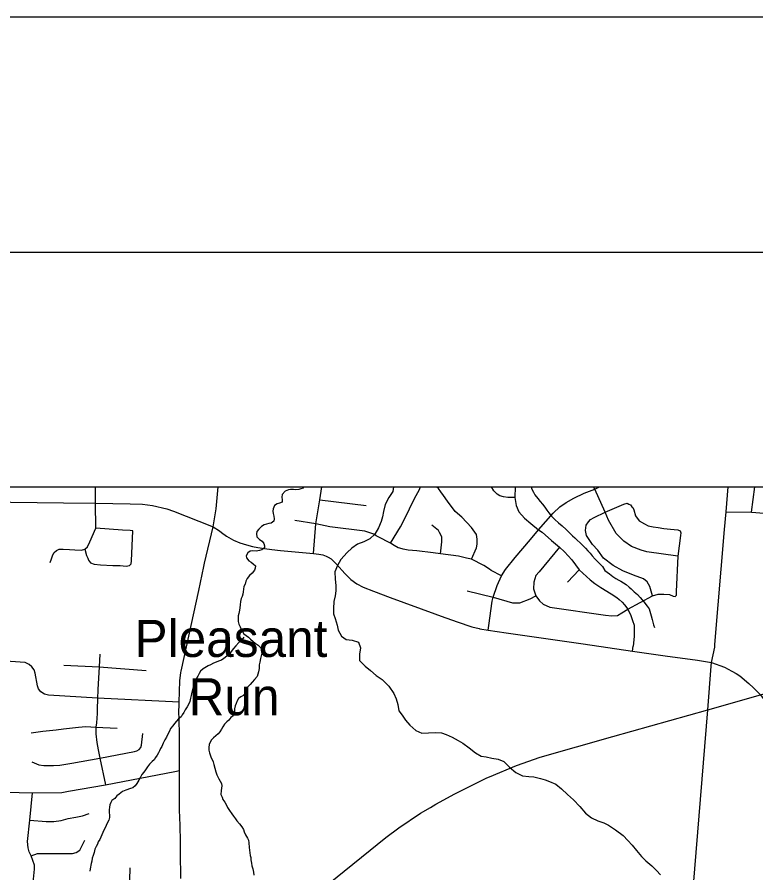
# Model space of a CAD drawing. Extents: x 0 to 34, y 0 to 22.
# Drawn here: x 5.399 to 6.973, y 20.179 to 22 of the extents above; entities that cross this region are included whole.
import ezdxf

# ---------------------------------------------------------------- set-up
doc = ezdxf.new("R2010")
doc.units = 0
for name, color, linetype in [('GM_X_City_Street', 7, 'Continuous'), ('GM_X_County_Road', 7, 'Continuous'), ('GM_X_Interstate_Route', 7, 'Continuous'), ('GM_X_Minor_River', 7, 'Continuous'), ('GM_X_Township_Subdivision', 7, 'Continuous'), ('GM_X_Unincorporated_Text', 7, 'Continuous'), ('GM_X_US_Route', 7, 'Continuous'), ('SH_Border', 7, 'Continuous'), ('SH_Cut_Line', 7, 'Continuous'), ('SH_Data', 7, 'Continuous')]:
    doc.layers.add(name, color=color, linetype=linetype)

msp = doc.modelspace()

# ---------------------------------------------------------------- linework, layer by layer
at = {"layer": 'GM_X_City_Street'}
for points in [[(6.3832, 20.6986), (6.3849, 20.6981), (6.4022, 20.695), (6.4405, 20.6893), (6.605, 20.6658), (6.7096, 20.6506), (6.7795, 20.6409), (6.8483, 20.6312), (6.8782, 20.6263), (6.9055, 20.6167), (6.9213, 20.6082), (6.9304, 20.6028)], [(6.4022, 20.695), (6.4035, 20.7049)], [(6.7096, 20.6506), (6.7109, 20.6612)], [(6.8782, 20.6263), (6.8849, 20.6592), (6.8854, 20.665)], [(6.7405, 19.0079), (6.7405, 19.0079), (6.7657, 19.288), (6.7742, 19.3827), (6.7997, 19.6706), (6.8028, 19.7088), (6.8332, 20.0742), (6.8703, 20.5257), (6.8776, 20.6185)], [(6.8776, 20.6185), (6.8782, 20.6263)], [(6.9304, 20.6028), (6.9384, 20.598), (6.9578, 20.5819), (6.9677, 20.5727), (6.9821, 20.5579), (6.9976, 20.5368), (7.0156, 20.5042), (7.0369, 20.4622), (7.0524, 20.431), (7.0619, 20.4131), (7.0736, 20.3904)], [(5.7352, 20.3947), (5.7449, 20.3966)]]:
    msp.add_lwpolyline(points, dxfattribs=at)
at = {"layer": 'GM_X_County_Road'}
for points in [[(6.8854, 20.665), (6.9059, 20.9098), (6.9091, 20.9473), (6.9137, 21)], [(5.3429, 20.9683), (5.3857, 20.9676), (5.4981, 20.9661), (5.5663, 20.9653), (5.6398, 20.9643), (5.6661, 20.9637), (5.6877, 20.9605), (5.7182, 20.9531), (5.7325, 20.9484), (5.786, 20.9271), (5.8166, 20.9148)], [(5.8166, 20.9148), (5.8302, 20.9069), (5.8343, 20.9031), (5.8448, 20.8953), (5.8598, 20.8869), (5.8736, 20.881), (5.8879, 20.8765), (5.9007, 20.8732), (5.9118, 20.8713), (5.926, 20.8693), (5.942, 20.8668), (5.9602, 20.8648), (6.0301, 20.8581), (6.0417, 20.8568), (6.0502, 20.8553), (6.0573, 20.8526), (6.0618, 20.8504), (6.0678, 20.8469), (6.0791, 20.8358), (6.0974, 20.8159), (6.1102, 20.8027), (6.1228, 20.7937), (6.1362, 20.7869), (6.1585, 20.7779), (6.194, 20.7649), (6.2889, 20.7299), (6.3022, 20.7249), (6.3362, 20.7129), (6.3678, 20.7026), (6.3832, 20.6986)], [(5.375, 20.3502), (5.4319, 20.3493), (5.4945, 20.35), (5.5087, 20.3522), (5.5871, 20.3662), (5.7352, 20.3947)]]:
    msp.add_lwpolyline(points, dxfattribs=at)
at = {"layer": 'GM_X_Interstate_Route'}
for points in [[(6.4056, 20.3832), (6.4626, 20.4073), (6.5132, 20.4247), (6.6681, 20.4691), (6.8703, 20.5257), (6.9821, 20.5579), (7.3247, 20.6555), (7.624, 20.7407), (7.6888, 20.7597), (7.7242, 20.769), (7.855, 20.8068), (7.91, 20.8216)], [(6.2913, 20.3246), (6.3311, 20.3471), (6.3995, 20.3807), (6.4056, 20.3832)], [(5.8297, 19.9667), (5.8374, 19.973), (5.8497, 19.9841), (5.9922, 20.0984), (6.1844, 20.2537), (6.2121, 20.2744), (6.2584, 20.306), (6.2797, 20.318), (6.2913, 20.3246)]]:
    msp.add_lwpolyline(points, dxfattribs=at)
at = {"layer": 'GM_X_Minor_River'}
for points in [[(5.9698, 20.9909), (5.9636, 20.9842), (5.9627, 20.9781), (5.9637, 20.9728), (5.964, 20.9674), (5.9579, 20.9653), (5.9533, 20.9638), (5.9475, 20.9605), (5.9444, 20.9534), (5.9439, 20.9488), (5.9445, 20.9435), (5.9459, 20.9377), (5.9466, 20.9324), (5.9461, 20.9275), (5.9403, 20.923), (5.9354, 20.922), (5.9254, 20.9191), (5.9197, 20.9158), (5.9142, 20.9099), (5.91, 20.9054), (5.9087, 20.9005), (5.9101, 20.894), (5.9153, 20.8885), (5.921, 20.8846), (5.9246, 20.8796), (5.9261, 20.875), (5.9264, 20.8704), (5.9202, 20.866), (5.9152, 20.8649), (5.9084, 20.8632), (5.9008, 20.8641), (5.8958, 20.8631), (5.8905, 20.8601), (5.8869, 20.8537), (5.8876, 20.8488), (5.8928, 20.8426), (5.8977, 20.8398), (5.9021, 20.8367), (5.9066, 20.8324), (5.9061, 20.8275), (5.9045, 20.8229), (5.8998, 20.8166), (5.894, 20.8114), (5.8894, 20.805), (5.8866, 20.7997), (5.8846, 20.7929), (5.8822, 20.788), (5.8813, 20.7827), (5.8808, 20.7766), (5.88, 20.7717), (5.8783, 20.7668), (5.8767, 20.7623), (5.8751, 20.7562), (5.8746, 20.7494), (5.8737, 20.7429), (5.8728, 20.738), (5.8712, 20.7308), (5.8703, 20.7255), (5.8698, 20.7187), (5.8701, 20.7133), (5.8715, 20.708), (5.874, 20.7022), (5.8762, 20.6976), (5.8795, 20.6922), (5.8821, 20.6876), (5.8869, 20.6837), (5.8918, 20.6806), (5.8963, 20.6763), (5.9018, 20.6712), (5.9063, 20.6677), (5.9123, 20.6634), (5.9175, 20.6584), (5.9208, 20.653), (5.9203, 20.6465), (5.9178, 20.6348), (5.9158, 20.6268), (5.9149, 20.6211), (5.9144, 20.6136), (5.9131, 20.6064), (5.9118, 20.6014), (5.9106, 20.5965), (5.9048, 20.5902), (5.9001, 20.5846), (5.8958, 20.5797), (5.89, 20.5737), (5.888, 20.5688), (5.8875, 20.5639), (5.8859, 20.5594), (5.8813, 20.5564), (5.8759, 20.5531), (5.8709, 20.5501), (5.8678, 20.5449), (5.8658, 20.5388), (5.8634, 20.5339), (5.8621, 20.5275), (5.862, 20.5222), (5.8615, 20.5176), (5.8596, 20.5131), (5.8545, 20.509), (5.8503, 20.5038), (5.8456, 20.5004)], [(6.0085, 21), (6.0083, 20.9977), (6.0037, 20.9959), (5.9991, 20.9945), (5.993, 20.9942), (5.9877, 20.9947), (5.9816, 20.9948), (5.9771, 20.9938), (5.9698, 20.9909)], [(6.201, 21), (6.1994, 20.9904), (6.1911, 20.9777), (6.1832, 20.9626), (6.1794, 20.9479), (6.1772, 20.9365), (6.1743, 20.9263), (6.1687, 20.9128), (6.1612, 20.8993), (6.1503, 20.8893), (6.1376, 20.8831), (6.1242, 20.8781), (6.1123, 20.8696), (6.1022, 20.8604), (6.0885, 20.8455), (6.0814, 20.8331), (6.0761, 20.8191), (6.0765, 20.8039), (6.0781, 20.7906), (6.0778, 20.7792), (6.0764, 20.7686), (6.0739, 20.7564), (6.0727, 20.7413), (6.0732, 20.7298), (6.0764, 20.7199), (6.0806, 20.7057), (6.083, 20.6954), (6.0899, 20.6827), (6.1, 20.6756), (6.1129, 20.6737), (6.1261, 20.67), (6.1303, 20.6577), (6.1281, 20.6441), (6.1282, 20.6304), (6.1408, 20.6183), (6.1519, 20.6093), (6.1642, 20.5987), (6.1769, 20.5904), (6.1906, 20.5757), (6.2016, 20.5602), (6.2063, 20.5487), (6.2102, 20.5372), (6.2121, 20.5238), (6.2191, 20.5141), (6.2265, 20.5037), (6.2357, 20.4928), (6.2487, 20.4815), (6.2611, 20.4762), (6.2755, 20.4767), (6.2904, 20.4774), (6.3033, 20.4768), (6.313, 20.4731), (6.3258, 20.4678), (6.3382, 20.4607), (6.3483, 20.4548), (6.3617, 20.4449), (6.3751, 20.4343), (6.3875, 20.4272), (6.3981, 20.4254), (6.4105, 20.4228), (6.4234, 20.4206), (6.4358, 20.4154), (6.448, 20.4033), (6.4614, 20.3923), (6.4753, 20.3852), (6.4893, 20.3837), (6.4999, 20.3827), (6.5139, 20.3793), (6.5237, 20.3768), (6.5334, 20.3731), (6.5462, 20.3675), (6.5589, 20.3573), (6.5715, 20.3456)], [(6.4943, 21), (6.4956, 20.9956), (6.4993, 20.9887), (6.5018, 20.9833), (6.5085, 20.9756), (6.5133, 20.969), (6.5181, 20.9632), (6.5229, 20.957), (6.5274, 20.9508), (6.5318, 20.945), (6.5374, 20.9381), (6.5444, 20.9307), (6.5519, 20.9237), (6.5601, 20.9171), (6.5683, 20.9093), (6.5757, 20.9023), (6.5821, 20.8961), (6.5869, 20.8915), (6.5921, 20.8868), (6.5981, 20.8813), (6.61, 20.8697), (6.6144, 20.8643), (6.6193, 20.8589), (6.6241, 20.8531), (6.63, 20.8465), (6.636, 20.8403), (6.646, 20.8309), (6.6508, 20.8225), (6.6609, 20.8154), (6.6676, 20.8096), (6.674, 20.8049), (6.6804, 20.8017), (6.6853, 20.7993), (6.6905, 20.7962), (6.6965, 20.7923), (6.7029, 20.7868), (6.7073, 20.7829), (6.7137, 20.7771), (6.7204, 20.7709), (6.7259, 20.7647)], [(6.7259, 20.7647), (6.7341, 20.7554), (6.7411, 20.7465), (6.7452, 20.7407), (6.7484, 20.7308), (6.7498, 20.7254), (6.7516, 20.7178), (6.753, 20.712), (6.7548, 20.7063), (6.7565, 20.7009)], [(5.8823, 20.6804), (5.8784, 20.6755), (5.8711, 20.6688), (5.8652, 20.6617), (5.8598, 20.6561), (5.8551, 20.6497), (5.8512, 20.6449), (5.8462, 20.64), (5.8396, 20.6352), (5.8342, 20.6315), (5.8281, 20.6293), (5.8231, 20.6272), (5.8174, 20.625), (5.8113, 20.6213), (5.8059, 20.6195), (5.7955, 20.6129), (5.7901, 20.6077), (5.7866, 20.6032), (5.7838, 20.5971), (5.7807, 20.5915), (5.7783, 20.5866), (5.7759, 20.5806), (5.7739, 20.5749), (5.7726, 20.5688), (5.7714, 20.5632), (5.7697, 20.556), (5.7685, 20.5507), (5.7672, 20.5435), (5.764, 20.5371), (5.7612, 20.5318), (5.7569, 20.5258), (5.7542, 20.5201), (5.751, 20.5149), (5.7483, 20.5104), (5.7429, 20.5067), (5.739, 20.5014), (5.7347, 20.4966), (5.7312, 20.4913), (5.7262, 20.4861), (5.7238, 20.4804), (5.7198, 20.4725), (5.7171, 20.4676), (5.7139, 20.462), (5.7103, 20.4548), (5.7072, 20.4477), (5.7048, 20.4432), (5.7024, 20.4386), (5.7004, 20.4341), (5.6977, 20.4292), (5.6942, 20.424), (5.6914, 20.4191), (5.6868, 20.4158), (5.6813, 20.4098), (5.6767, 20.4042), (5.6724, 20.3978), (5.6692, 20.3933), (5.665, 20.388), (5.6618, 20.3824), (5.6583, 20.376), (5.6543, 20.3689), (5.6508, 20.364), (5.6458, 20.3599), (5.6405, 20.3585), (5.6305, 20.3549), (5.624, 20.3516), (5.6163, 20.346), (5.6117, 20.3423), (5.607, 20.3371), (5.6008, 20.333), (5.5985, 20.3285), (5.5968, 20.3232), (5.596, 20.3183), (5.5951, 20.313), (5.5954, 20.3069), (5.596, 20.3012), (5.5959, 20.2962), (5.5943, 20.2909), (5.5919, 20.2857), (5.5888, 20.2796), (5.5868, 20.2747), (5.584, 20.2695), (5.5816, 20.2642), (5.58, 20.2597), (5.5772, 20.2544), (5.5752, 20.2499), (5.5717, 20.245), (5.5701, 20.2397), (5.5673, 20.2344), (5.5649, 20.2288), (5.5633, 20.2223), (5.5609, 20.2155), (5.5593, 20.2099), (5.558, 20.2034), (5.5571, 20.1985), (5.5546, 20.1871), (5.5538, 20.1822)], [(5.8456, 20.5004), (5.8406, 20.4952), (5.8371, 20.4892), (5.8343, 20.4843), (5.8312, 20.479), (5.8277, 20.4746), (5.8226, 20.4705), (5.8176, 20.466), (5.8133, 20.4615), (5.8106, 20.457), (5.8082, 20.4517), (5.8073, 20.4453), (5.8076, 20.4396), (5.809, 20.4339), (5.8115, 20.4254), (5.8166, 20.4147), (5.818, 20.4093), (5.8205, 20.4013), (5.8222, 20.3936), (5.8248, 20.3871), (5.8291, 20.3791), (5.8317, 20.3737), (5.8343, 20.3691), (5.8349, 20.3637), (5.8348, 20.3592), (5.8336, 20.3542), (5.8334, 20.3455), (5.8356, 20.3394), (5.8374, 20.3348), (5.8414, 20.329), (5.8447, 20.324), (5.8473, 20.3178), (5.8517, 20.3117), (5.8565, 20.3043), (5.8598, 20.2993), (5.8642, 20.2939), (5.8672, 20.2893), (5.8731, 20.2831), (5.8779, 20.2765), (5.8812, 20.2711), (5.8827, 20.2658), (5.8859, 20.2596), (5.8896, 20.2527), (5.8918, 20.2481), (5.8924, 20.2424), (5.8934, 20.2329), (5.8944, 20.2271), (5.8957, 20.2157), (5.8967, 20.2111), (5.897, 20.2062), (5.8984, 20.1993), (5.8994, 20.1936), (5.9012, 20.1871), (5.9026, 20.1802), (5.9032, 20.1737)], [(6.5715, 20.3456), (6.5845, 20.3339), (6.5978, 20.3202), (6.61, 20.3055), (6.6227, 20.2957), (6.6362, 20.2897), (6.6486, 20.2852), (6.6587, 20.28), (6.6737, 20.2701), (6.6897, 20.258), (6.6997, 20.2478), (6.7093, 20.2373), (6.7186, 20.2265), (6.7289, 20.2137), (6.7382, 20.2039), (6.7508, 20.1934), (6.7608, 20.184), (6.7693, 20.1743)]]:
    msp.add_lwpolyline(points, dxfattribs=at)
at = {"layer": 'GM_X_Township_Subdivision'}
for points in [[(5.4694, 20.839), (5.4724, 20.8471), (5.4753, 20.8553), (5.4781, 20.8608), (5.4828, 20.8647), (5.4887, 20.8673), (5.4971, 20.8675), (5.5105, 20.8671), (5.5223, 20.8663), (5.5364, 20.8657), (5.5437, 20.8675), (5.549, 20.8728), (5.5539, 20.883), (5.5672, 20.9123), (5.5663, 20.9653), (5.5663, 21)], [(6.0301, 20.8581), (6.0354, 20.9212), (6.044, 20.9727), (6.0481, 21)], [(6.1944, 20.8806), (6.2157, 20.9151), (6.2234, 20.9297), (6.2461, 20.9768), (6.2558, 20.9934), (6.2586, 21)], [(6.3666, 20.8461), (6.3777, 20.8706), (6.3789, 20.8785), (6.3788, 20.8888), (6.3773, 20.8987), (6.367, 20.9136), (6.3464, 20.9354), (6.3323, 20.9481), (6.3157, 20.97), (6.3074, 20.9818), (6.3015, 20.9895), (6.2966, 20.9964), (6.2929, 20.9997), (6.2925, 21)], [(6.4035, 20.7049), (6.4107, 20.7567), (6.413, 20.7651), (6.4213, 20.7905), (6.431, 20.8109), (6.4396, 20.8241), (6.46, 20.85), (6.4764, 20.8687), (6.4923, 20.8885), (6.5099, 20.909), (6.5406, 20.9444), (6.5548, 20.9578), (6.5688, 20.9666), (6.5846, 20.9759), (6.607, 20.9866), (6.6294, 20.9953), (6.6397, 21)], [(6.459, 20.9777), (6.444, 20.9779), (6.4354, 20.9788), (6.4271, 20.9814), (6.4214, 20.9845), (6.4142, 20.9919), (6.4098, 21)], [(6.4602, 21), (6.459, 20.9777), (6.462, 20.9607), (6.4676, 20.9467), (6.4798, 20.9337), (6.4931, 20.922), (6.5099, 20.909), (6.5171, 20.9035), (6.5373, 20.8862), (6.5542, 20.8716), (6.5651, 20.8617), (6.5803, 20.8449), (6.5963, 20.8235), (6.6198, 20.8025), (6.6297, 20.7945), (6.6426, 20.786), (6.6644, 20.7724), (6.6764, 20.7646), (6.6813, 20.7603), (6.6875, 20.755), (6.6926, 20.749), (6.7001, 20.7401), (6.7061, 20.7263), (6.7098, 20.7161), (6.7131, 20.7057), (6.7134, 20.682), (6.7109, 20.6612)], [(6.8063, 20.853), (6.7402, 20.8617), (6.7281, 20.8656), (6.7077, 20.8734), (6.6913, 20.8848), (6.6748, 20.9006), (6.6588, 20.929), (6.6515, 20.9464), (6.6294, 20.9953), (6.6269, 21)], [(6.9091, 20.9473), (6.963, 20.9464), (7.0256, 20.9416), (7.061, 20.9337), (7.0802, 20.9306), (7.0895, 20.9304), (7.1023, 20.9323), (7.1174, 20.9395), (7.1268, 20.9457), (7.1446, 20.9641), (7.1673, 20.9877), (7.1788, 21)], [(6.963, 20.9464), (6.9702, 21)], [(6.044, 20.9727), (6.1425, 20.9606)], [(6.7524, 20.7685), (6.7513, 20.7735), (6.7467, 20.7881), (6.7412, 20.798), (6.7333, 20.8043), (6.7121, 20.8123), (6.6889, 20.8212), (6.6683, 20.8331), (6.6484, 20.8486), (6.6358, 20.8652), (6.6244, 20.8773), (6.6121, 20.8965), (6.6098, 20.907), (6.6113, 20.9187), (6.6158, 20.9261), (6.6205, 20.9306), (6.6283, 20.935), (6.6515, 20.9464), (6.6915, 20.9631), (6.6987, 20.9652), (6.702, 20.9637), (6.7055, 20.9617), (6.7087, 20.9579)], [(6.7087, 20.9579), (6.7102, 20.9564), (6.7127, 20.9514), (6.7164, 20.9382), (6.7241, 20.9282), (6.7351, 20.9212), (6.7435, 20.9171), (6.7536, 20.915), (6.7645, 20.9136), (6.7766, 20.9117), (6.791, 20.9101), (6.8064, 20.9085), (6.8113, 20.9063), (6.8128, 20.9027), (6.8118, 20.8965), (6.8063, 20.853), (6.803, 20.7773), (6.803, 20.7726), (6.8031, 20.7689)], [(6.164, 20.8963), (6.1586, 20.8994), (6.1502, 20.9024), (6.1399, 20.9061), (6.0649, 20.9151), (6.0354, 20.9212), (5.991, 20.9287)], [(5.5437, 20.8675), (5.5468, 20.8542), (5.5495, 20.8485), (5.5513, 20.8444), (5.5556, 20.8384), (5.5633, 20.8357), (5.5765, 20.8345), (5.6032, 20.8331), (5.6187, 20.8329), (5.6317, 20.8317), (5.6389, 20.8325), (5.6423, 20.8365), (5.6431, 20.8431), (5.6458, 20.9064), (5.6397, 20.907), (5.6238, 20.9078), (5.5672, 20.9123)], [(6.3007, 20.8578), (6.3037, 20.883), (6.3041, 20.8929), (6.3014, 20.8982), (6.2991, 20.9031), (6.2963, 20.9074), (6.2826, 20.9184)], [(6.405, 20.8249), (6.3933, 20.833), (6.3666, 20.8461), (6.3563, 20.8485), (6.3393, 20.8525), (6.3007, 20.8578), (6.2851, 20.86), (6.2504, 20.8637), (6.2323, 20.8655), (6.2215, 20.8677), (6.2145, 20.8695), (6.2104, 20.8707), (6.2024, 20.8752), (6.1944, 20.8806), (6.1679, 20.8941), (6.164, 20.8963)], [(6.5542, 20.8716), (6.5108, 20.8195), (6.5042, 20.8115), (6.4994, 20.7975), (6.4991, 20.783), (6.5041, 20.7686), (6.5114, 20.7579), (6.5196, 20.7505), (6.5339, 20.7442), (6.652, 20.7272), (6.666, 20.7259), (6.678, 20.7267), (6.687, 20.7322), (6.7001, 20.7401), (6.7524, 20.7685), (6.7642, 20.7715), (6.7762, 20.7716), (6.7889, 20.7709), (6.7962, 20.7678), (6.8005, 20.7672), (6.8031, 20.7689)], [(6.431, 20.8109), (6.4089, 20.8222), (6.405, 20.8249)], [(6.5712, 20.7976), (6.5963, 20.8235)], [(6.3578, 20.7792), (6.413, 20.7651), (6.454, 20.7537), (6.4697, 20.7537), (6.492, 20.7616), (6.5041, 20.7686)], [(5.5757, 20.644), (5.5741, 20.6169), (5.5712, 20.5688)], [(5.7442, 20.5423), (5.5702, 20.5504), (5.4658, 20.5568), (5.4576, 20.5588), (5.4496, 20.5641), (5.4445, 20.5703), (5.4423, 20.5768), (5.4376, 20.6034), (5.4352, 20.6107), (5.4308, 20.617), (5.4252, 20.6223), (5.4165, 20.6261), (5.3647, 20.6298), (5.3631, 20.6296)], [(5.4987, 20.621), (5.5741, 20.6169), (5.6742, 20.6095)], [(5.5712, 20.5688), (5.5712, 20.5677), (5.5702, 20.5504), (5.5698, 20.5257)], [(5.5698, 20.5257), (5.5697, 20.5178), (5.5682, 20.498), (5.5671, 20.489), (5.5672, 20.4749), (5.5689, 20.4562), (5.572, 20.4402), (5.5754, 20.4229), (5.5871, 20.3662)], [(5.4292, 20.477), (5.4539, 20.4803), (5.4823, 20.4834), (5.4981, 20.4849), (5.5297, 20.4887), (5.5454, 20.4903), (5.5671, 20.489), (5.6126, 20.4866)], [(5.4308, 20.4152), (5.4456, 20.4088), (5.4563, 20.4068), (5.4765, 20.4068), (5.4905, 20.4079), (5.5157, 20.4124), (5.5754, 20.4229), (5.6489, 20.4368), (5.6541, 20.4385), (5.6595, 20.4414), (5.6628, 20.4455), (5.6644, 20.4504), (5.6668, 20.4756)], [(5.4362, 20.193), (5.4362, 20.1953), (5.4292, 20.2149), (5.425, 20.2233), (5.423, 20.232), (5.4215, 20.2455), (5.426, 20.2908), (5.4319, 20.3493)], [(5.426, 20.2908), (5.4611, 20.288), (5.4775, 20.288), (5.4927, 20.2903), (5.5081, 20.294), (5.5243, 20.297), (5.5384, 20.3002), (5.5529, 20.3049)], [(5.4292, 20.2149), (5.4427, 20.2196), (5.4536, 20.2199), (5.5173, 20.2201), (5.5253, 20.2218), (5.533, 20.2271), (5.5432, 20.248)], [(5.6551, 20.116), (5.6413, 20.1054), (5.6314, 20.0955), (5.6217, 20.085), (5.6112, 20.0715), (5.5905, 20.044), (5.5797, 20.0265), (5.5633, 20), (5.5497, 19.9764), (5.547, 19.9724), (5.5436, 19.9704), (5.5382, 19.9696), (5.4722, 19.9699), (5.4324, 19.9701), (5.4245, 19.9734), (5.4197, 19.977), (5.418, 19.9823), (5.4242, 20.0517), (5.4344, 20.1652), (5.4363, 20.1866), (5.4362, 20.1924), (5.4362, 20.193)], [(5.6918, 20.0681), (5.6551, 20.116), (5.6522, 20.1198), (5.6467, 20.1298), (5.6422, 20.1426), (5.6393, 20.163), (5.6403, 20.1891)]]:
    msp.add_lwpolyline(points, dxfattribs=at)
at = {"layer": 'GM_X_US_Route'}
for points in [[(5.8166, 20.9148), (5.8233, 20.9535), (5.8273, 21)], [(5.7986, 20.8375), (5.8166, 20.9148)], [(5.7859, 20.7794), (5.7971, 20.8309), (5.7986, 20.8375)], [(5.7482, 20.6048), (5.7486, 20.6081), (5.7859, 20.7794)], [(5.7439, 20.5157), (5.7442, 20.5423), (5.746, 20.5874), (5.7482, 20.6048)], [(5.7449, 20.4661), (5.744, 20.5116), (5.7439, 20.5155), (5.7439, 20.5157)], [(5.745, 20.3774), (5.7449, 20.3966), (5.7452, 20.4494), (5.7449, 20.4661)], [(5.7456, 20.3008), (5.7454, 20.308), (5.745, 20.3774)], [(5.7474, 20.2147), (5.7471, 20.2495), (5.7456, 20.3008)], [(5.7476, 20.1668), (5.7477, 20.1736), (5.7474, 20.2147)]]:
    msp.add_lwpolyline(points, dxfattribs=at)
at = {"layer": 'SH_Border'}
msp.add_lwpolyline([(1.5, 21.5), (33.5, 21.5), (33.5, 0.5), (1.5, 0.5)], close=True, dxfattribs=at)
at = {"layer": 'SH_Cut_Line'}
msp.add_lwpolyline([(0, 0), (34, 0), (34, 22), (0, 22)], close=True, dxfattribs=at)
at = {"layer": 'SH_Data'}
msp.add_line((2, 21), (8.8, 21), dxfattribs=at)

# ---------------------------------------------------------------- texts
at = {"layer": 'GM_X_Unincorporated_Text'}
for s, p in [('Pleasant', (5.6492, 20.6382)), ('Run', (5.7642, 20.514))]:
    msp.add_text(s, height=0.07898, rotation=0, dxfattribs=at).set_placement(p)

doc.saveas('drawing.dxf')
